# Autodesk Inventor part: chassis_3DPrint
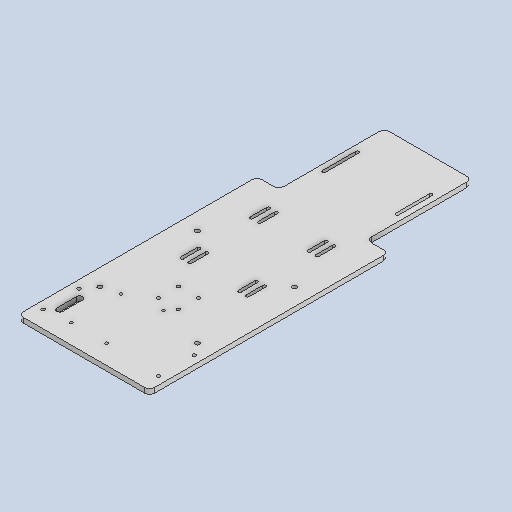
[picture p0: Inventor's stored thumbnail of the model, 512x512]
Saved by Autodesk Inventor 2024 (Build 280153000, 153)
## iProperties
Created: 2022-11
Part Number: chassis_3DPrint
Material: Generic
Document SubType Name: Modeling
Designer: Thomas
Density: 1 g/cm^3
Appearance: Default
Author: Thomas
Created: 2022-09
Part Number: chassis
Material: Générique
Designer: ropertth
Appearance: Par défaut
Mass: 199.944 g
Surface Area: 883.822 cm^2
Volume: 199.944 cm^3
Author: ropertth
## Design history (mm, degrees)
sketch "Esquisse1"
  geometry: L1 (66, 120)-(-66, 120); L2 (-66, 120)-(-66, -120); L3 (66, -120)-(66, 120); L4 (66, 120)-(-66, -120); L5 (-66, 120)-(66, -120); L6 (-44, -120)-(-44, -226); L7 (-44, -226)-(44, -226); L8 (44, -226)-(44, -120); L9 (-66, -120)-(-44, -120); L10 (44, -120)-(66, -120); 1 further point
  constraints: 20 end point, 4 parallel, 2 midpoint, 1 horizontal, 1 perpendicular
  dimensions: "d0" = 240 distance of L3.start L1.start; "d1" = 132 distance of L2.end L3.start; "d2" = 88 distance of L6.end L7.end; "d3" = 44 distance from line of point (0, 0) L8; "d5" = 346 distance between parallel lines of L7 L1
extrude "Extrusion1" new body sketch "Esquisse1" distance "d6" = 5; taper "d7" = 0 deg
fillet "Congé1" dims "d8" = 5
sketch "Esquisse3"
  geometry: L1 (-61, -120)-(61, -120) reference; L2 (-66, 115)-(-66, -115) reference; 2 further points
  dimensions: "d31" = 17 distance from line of L1 point (-58, -103); "d32" = 8 distance from line of L2 point (-58, -103)
hole "Perçage2" sketch "Esquisse3" diameter "d24" = 3.5; stored, may be unused: countersink angle "d28" = 90 deg, drill point angle "d30" = 118 deg; dims "d25" = 6, "d26" = 4, "d27" = 2, "d29" = 8
pattern_linear "Réseau rectangulaire2" dims "d35" = 36, "d38" = 116
sketch "Esquisse4"
  geometry: L1 (-49.4, -75)-(-49.4, -95); L2 (-52.4, -75)-(-52.4, -95); L3 (-46.4, -95)-(-46.4, -75); L4 (66, -115)-(66, 115) reference; L5 (-61, -120)-(61, -120) reference; L6 (-66, 115)-(-66, -115) reference; A1 r 3 centre (-49.4, -75) between (-46.4, -75) and (-52.4, -75); A2 r 3 centre (-49.4, -95) between (-52.4, -95) and (-46.4, -95); 2 further points
  constraints: 8 end point, 4 point on circle, 4 tangent, 2 centre point, 1 midpoint, 1 parallel, 1 vertical
  dimensions: "d39" = 3 radius of A2; "d41" = 35 distance from line of L5 point (-49.4, -85); "d42" = 20 distance of L1.start L1.end; "d45" = 16.6 distance between parallel lines of L6 L1
extrude "Extrusion2" cut sketch "Esquisse4" extent not by distance; stored distance "d43" = 0; taper "d44" = 0 deg
sketch "Esquisse5"
  geometry: L1 (-61, 120)-(61, 120) reference; L2 (-66, -115)-(-66, 115) reference; 2 further points
  dimensions: "d53" = 19.5 distance from line of L1 point (3.4, 100.5); "d54" = 69.4 distance from line of L2 point (3.4, 100.5)
hole "Perçage3" sketch "Esquisse5" diameter "d46" = 3; stored, may be unused: countersink angle "d50" = 90 deg, drill point angle "d52" = 118 deg; dims "d47" = 6, "d48" = 4, "d49" = 2, "d51" = 8
pattern_linear "Réseau rectangulaire3" dims "d57" = 57
sketch "Esquisse6"
  geometry: L1 (-61, 120)-(61, 120) reference; L2 (-66, -115)-(-66, 115) reference; 2 further points
  dimensions: "d65" = 19.5 distance from line of L1 point (-32.3, 100.5); "d66" = 33.7 distance from line of L2 point (-32.3, 100.5)
hole "Perçage4" sketch "Esquisse6" diameter "d58" = 3; stored, may be unused: countersink angle "d62" = 90 deg, drill point angle "d64" = 0 deg; dims "d59" = 6, "d60" = 4, "d61" = 2, "d63" = 6
pattern_linear "Réseau rectangulaire4" dims "d69" = 50
sketch "Esquisse7"
  geometry: L1 (-37, -192)-(-37, -158); L2 (-38.5, -192)-(-38.5, -158); L3 (-35.5, -158)-(-35.5, -192); L4 (39, -226)-(-39, -226) reference; L5 (-44, -221)-(-44, -125) reference; A1 r 1.5 centre (-37, -192) between (-38.5, -192) and (-35.5, -192); A2 r 1.5 centre (-37, -158) between (-35.5, -158) and (-38.5, -158); 2 further points
  constraints: 8 end point, 4 point on circle, 4 tangent, 2 centre point, 1 midpoint, 1 parallel, 1 vertical
  dimensions: "d70" = 1.5 radius of A2; "d71" = 34 distance from line of L4 L1.start; "d72" = 34 distance of L1.start L1.end; "d73" = 7 distance between parallel lines of L1 L5
extrude "Extrusion3" cut sketch "Esquisse7" extent not by distance; stored distance "d74" = 0; taper "d75" = 0 deg
mirror "Symétrie1"
sketch "Sketch8"
  geometry: L1 (-61, -120)-(61, -120) reference; L2 (0, -120)-(0, 226); L3 (39, 226)-(-39, 226) reference; 5 further points
  constraints: 2 end point, 2 midpoint, 1 horizontal, 1 vertical, 3 other
  dimensions: "d86" = 98 distance of point (49, -55) point (49, 43) (= pcb_fixation_ecart); "d89" = 98 distance of point (49, -55) point (-49, -55) (= pcb_fixation_ecart); "d92" = 49 distance from line of L2 point (49, -55) (= 0.5 x d89); "d93" = 65 distance from line of L1 point (49, -55)
hole "Hole5" sketch "Sketch8" at (49, -55), (49, 43), (-49, -55), (-49, 43) diameter "d76" = 4.5; stored, may be unused: countersink angle "d80" = 90 deg, drill point angle "d82" = 118 deg; dims "d77" = 6, "d78" = 3.6, "d79" = 2, "d81" = 8
sketch "Sketch9" dims "d102" = 10
  geometry: L1 (25, 11.5)-(25, 28.5); L2 (26.5, 11.5)-(26.5, 28.5); L3 (23.5, 28.5)-(23.5, 11.5); L4 (0, 0)-(47.798, 0); L5 (33, 11.5)-(33, 28.5); L6 (34.5, 11.5)-(34.5, 28.5); L7 (31.5, 28.5)-(31.5, 11.5); L8 (0, 0)-(0, 64.835); L9 (-25, 11.5)-(-25, 28.5); L10 (-33, 11.5)-(-33, 28.5); L11 (-31.5, 11.5)-(-31.5, 28.5); L12 (-34.5, 28.5)-(-34.5, 11.5); L13 (-26.5, 28.5)-(-26.5, 11.5); L14 (-23.5, 11.5)-(-23.5, 28.5); L15 (33, 81.5)-(33, 98.5); L16 (25, 81.5)-(25, 98.5); L17 (26.5, 81.5)-(26.5, 98.5); L18 (23.5, 98.5)-(23.5, 81.5); L19 (31.5, 98.5)-(31.5, 81.5); L20 (34.5, 81.5)-(34.5, 98.5); L21 (-25, 81.5)-(-25, 98.5); L22 (-33, 81.5)-(-33, 98.5); L23 (-31.5, 81.5)-(-31.5, 98.5); L24 (-34.5, 98.5)-(-34.5, 81.5); L25 (-26.5, 98.5)-(-26.5, 81.5); L26 (-23.5, 81.5)-(-23.5, 98.5); A1 r 1.5 centre (25, 11.5) between (23.5, 11.5) and (26.5, 11.5); A2 r 1.5 centre (25, 28.5) between (26.5, 28.5) and (23.5, 28.5); A3 r 1.5 centre (33, 11.5) between (31.5, 11.5) and (34.5, 11.5); A4 r 1.5 centre (33, 28.5) between (34.5, 28.5) and (31.5, 28.5); A5 r 1.5 centre (-33, 11.5) between (-34.5, 11.5) and (-31.5, 11.5); A6 r 1.5 centre (-25, 11.5) between (-26.5, 11.5) and (-23.5, 11.5); A7 r 1.5 centre (-33, 28.5) between (-31.5, 28.5) and (-34.5, 28.5); A8 r 1.5 centre (-25, 28.5) between (-23.5, 28.5) and (-26.5, 28.5); A9 r 1.5 centre (25, 81.5) between (23.5, 81.5) and (26.5, 81.5); A10 r 1.5 centre (33, 81.5) between (31.5, 81.5) and (34.5, 81.5); A11 r 1.5 centre (25, 98.5) between (26.5, 98.5) and (23.5, 98.5); A12 r 1.5 centre (33, 98.5) between (34.5, 98.5) and (31.5, 98.5); A13 r 1.5 centre (-33, 81.5) between (-34.5, 81.5) and (-31.5, 81.5); A14 r 1.5 centre (-25, 81.5) between (-26.5, 81.5) and (-23.5, 81.5); A15 r 1.5 centre (-33, 98.5) between (-31.5, 98.5) and (-34.5, 98.5); A16 r 1.5 centre (-25, 98.5) between (-23.5, 98.5) and (-26.5, 98.5); 24 further points
  constraints: 68 end point, 34 point on circle, 16 centre point, 4 tangent, 3 horizontal, 3 vertical, 1 midpoint, 1 parallel, 98 other
  dimensions: "d94" = 3 distance between parallel lines of L2 L3; "d95" = 20 distance of point (25, 10) point (25, 30); "d96" = 25 distance from line of L1 L4.start; "d99" = 8 distance of L2.start L6.start; "d115" = 58 distance of L2.end L11.end (= 2 x d96 + d99); "d118" = 70 distance of L2.end L17.end (computed from d95); "d123" = 20 distance from line of L4 point (25, 20)
extrude "Extrusion4" cut sketch "Sketch9" extent not by distance; stored distance "d121" = 0; taper "d122" = 0 deg
sketch "Sketch11"
  geometry: L1 (0, 0)-(22.96, 0); L2 (22.96, 0)-(0, 0); L3 (0, 13.489)-(0, 0); 4 further points
  constraints: 6 end point, 2 horizontal, 1 collinear, 1 perpendicular, 1 vertical, 3 other
  dimensions: "d131" = 10 horizontal distance of L1.start point (-10, -35); "d132" = 35 vertical distance of L1.start point (-10, -35); "d135" = 20 distance of point (-10, -35) point (10, -35) (= 2 x d131); "d138" = 20 distance of point (-10, -35) point (-10, -15)
hole "Hole6" sketch "Sketch11" at (-10, -35), (10, -35), (-10, -15), (10, -15) diameter "d124" = 3.4; stored, may be unused: countersink angle "d128" = 90 deg, drill point angle "d130" = 118 deg; dims "d125" = 6, "d126" = 6.3, "d127" = 2, "d129" = 8
node "Solide1"
other parameters: "pcb_fixation_ecart" = 98
